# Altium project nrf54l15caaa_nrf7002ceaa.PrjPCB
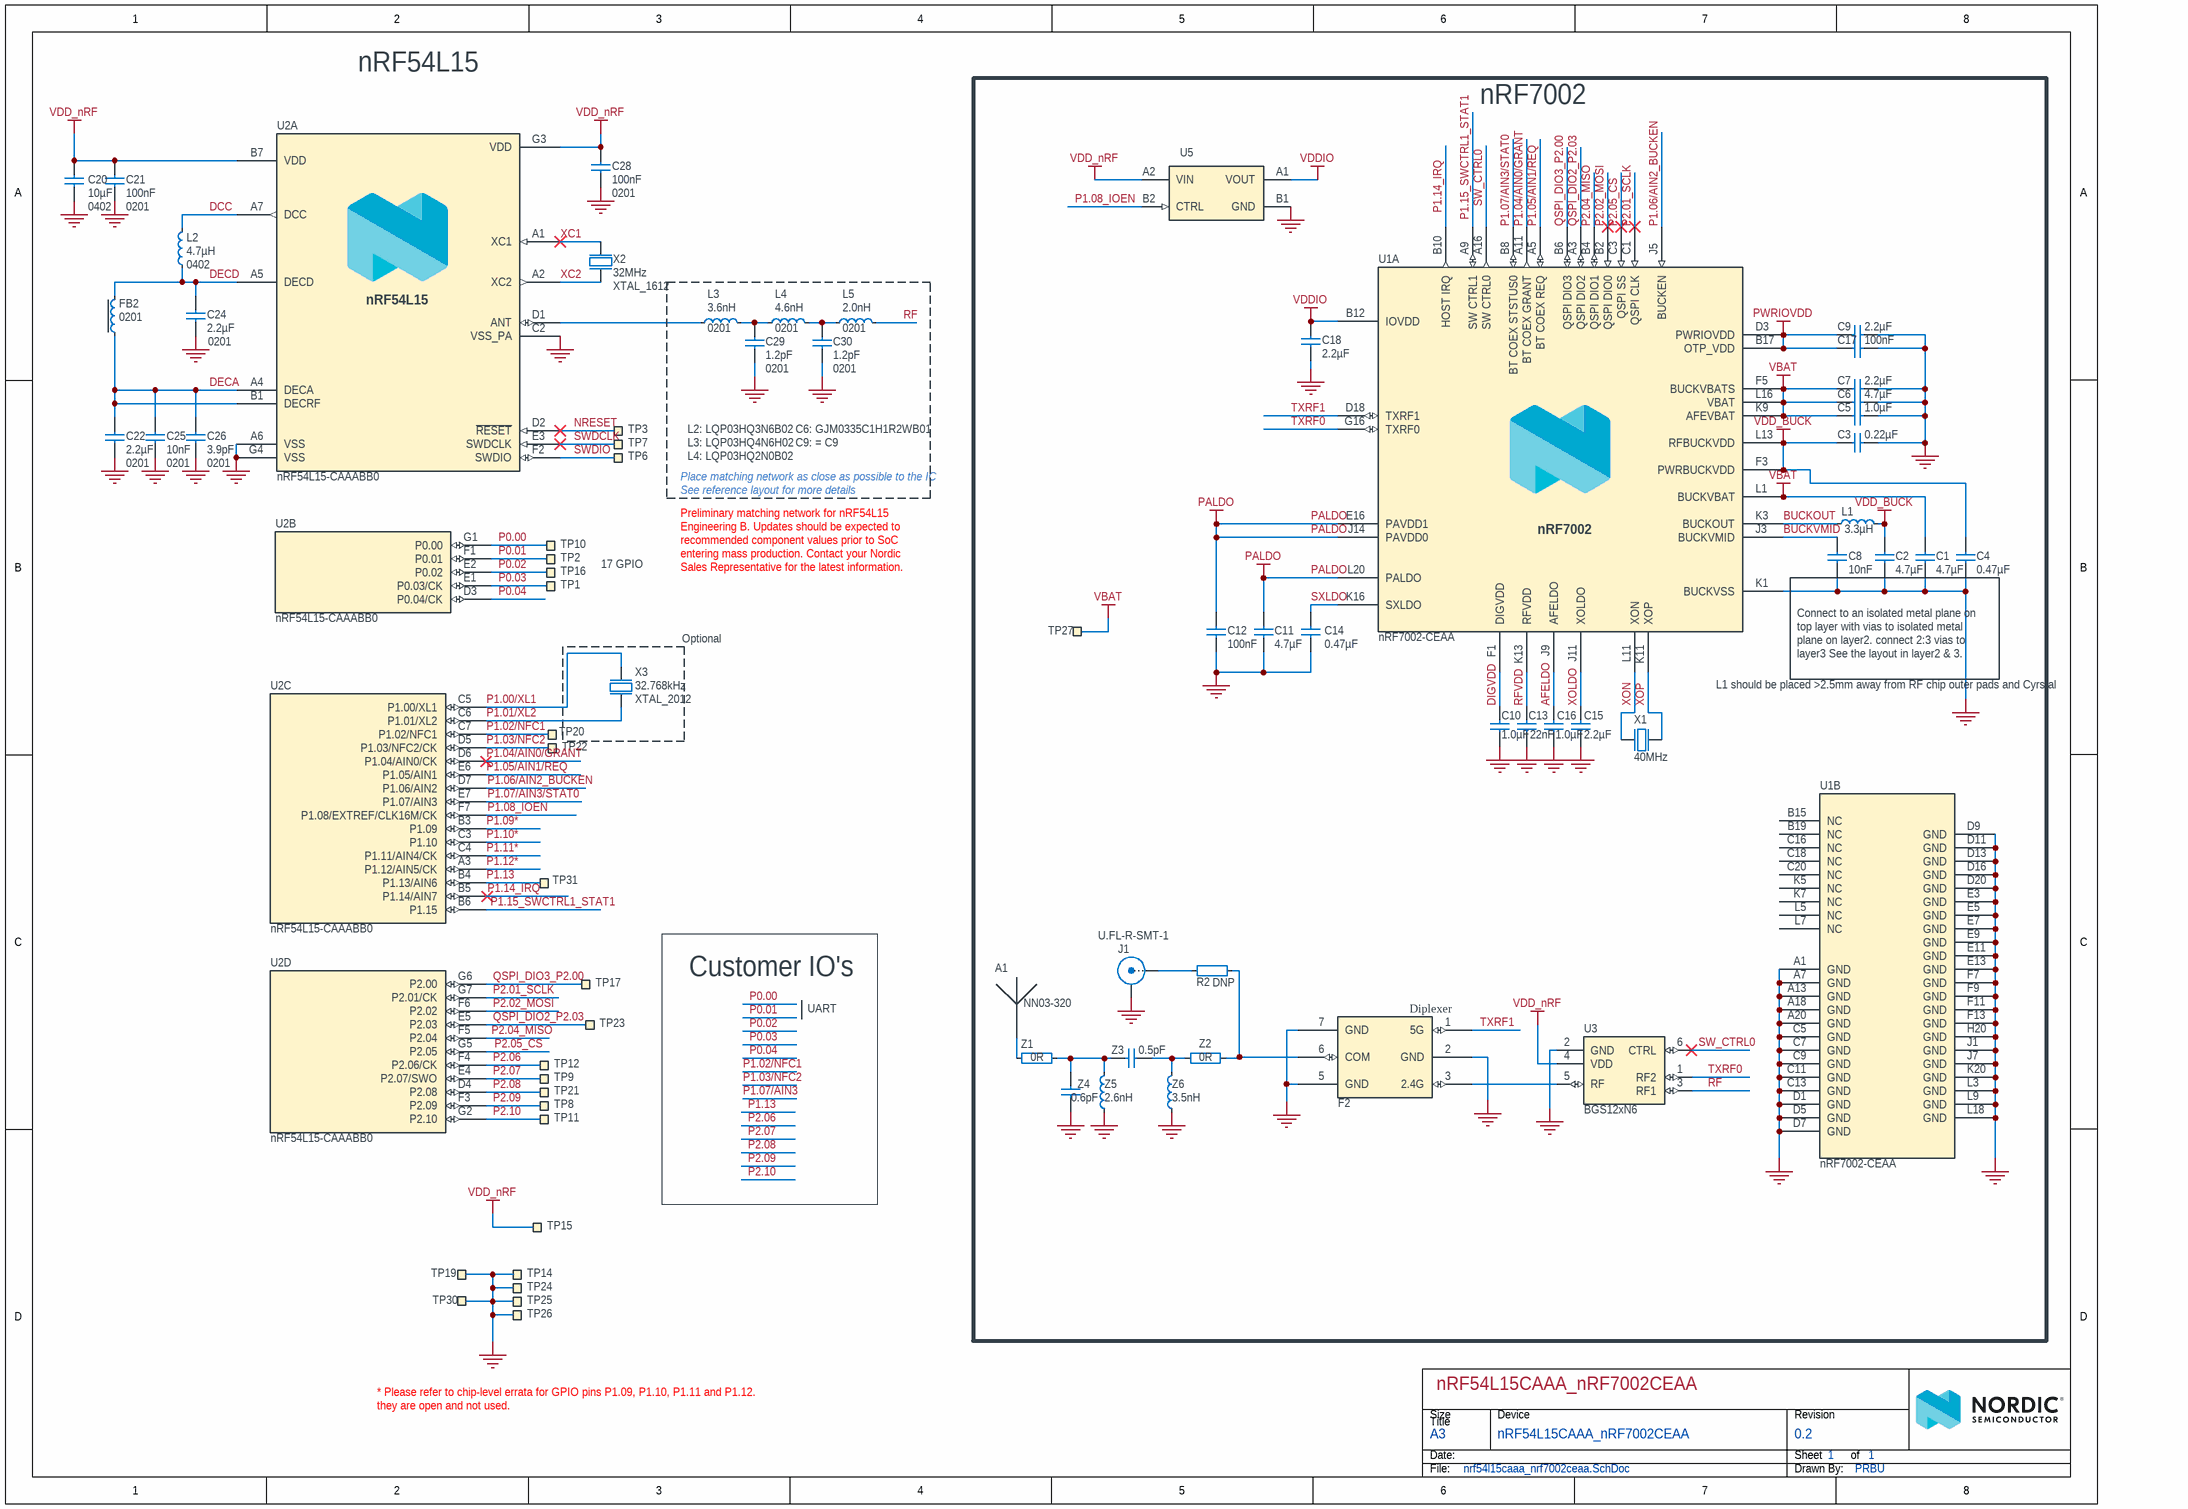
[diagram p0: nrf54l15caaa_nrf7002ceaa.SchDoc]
Revision: 0.2; RefLayoutTitle: nRF54L15CAAA_nRF7002CEAA; Device: nRF54L15CAAA_nRF7002CEAA; Classification: PRELIMINARY
1 sheet, 75 parts. Net scope: global (net labels, ports and power ports of the same name join across sheets).
Board file: nrf54l15caaa_nrf7002ceaa.PcbDoc

## Sheet nrf54l15caaa_nrf7002ceaa.SchDoc
size A3; Organization: Nordic Semiconductor; Revision: 0.2; SheetNumber: 1; SheetTotal: 1; DrawnBy: PRBU; DocumentSize: A3

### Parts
A1  NN03-320  [NN03-320]
C1  4.7µF  [CAPC1608X06L]
C2  4.7µF  [CAPC1608X06L]
C3  0.22µF  [CAPC0603X03L_C]
C4  0.47µF  [CAPC0603X03L_C]
C5  1.0µF  [CAPC1005X04L]
C6  4.7µF  [CAPC1608X06L]
C7  2.2µF  [CAPC1608X06L]
C8  10nF  [CAPC0603X03L_C]
C9  2.2µF  [CAPC1005X04L]
C10  1.0µF  [CAPC1005X04L]
C11  4.7µF  [CAPC1608X06L]
C12  100nF  [CAPC0603X03L_C]
C13  22nF  [CAPC0603X03L_C]
C14  0.47µF  [CAPC0603X03L_C]
C15  2.2µF  [CAPC0603X03L_C]
C16  1.0µF  [CAPC1005X04L]
C17  100nF  [CAPC0603X03L_C]
C18  2.2µF  [CAPC1005X04L]
C20  10µF  Footprint Doc: 0402  [CAPC1005X04L]
C21  100nF  Footprint Doc: 0201  [CAPC0603X03L_C]
C22  2.2µF  Footprint Doc: 0201  [CAPC0603X03L_C]
C24  2.2µF  Footprint Doc: 0201  [CAPC0603X03L_C]
C25  10nF  Footprint Doc: 0201  [CAPC0603X03L_C]
C26  3.9pF  Footprint Doc: 0201  [CAPC0603X03L_C]
C28  100nF  Footprint Doc: 0201  [CAPC0603X03L_C]
C29  1.2pF  Footprint Doc: 0201  [CAPC0603X03L_C]
C30  1.2pF  Footprint Doc: 0201  [CAPC0603X03L_C]
F2  LFD_5G_Diplexer  [CAF-50P160X80-6N]  (value not drawn)
FB2  Footprint Doc: 0201  [INDC0603X03L_C]  (hidden comment: 120R/0.2A)
J1  U.FL-R-SMT-1  [COAXIAL RF U.FL-R-SMT-1]
L1  3.3µH  [INDC2520X10N]
L2  4.7µH  Footprint Doc: 0402  [INDC1005X04L]
L3  3.6nH  Footprint Doc: 0201  [INDC0603X03L_C]
L4  4.6nH  Footprint Doc: 0201  [INDC0603X03L_C]
L5  2.0nH  Footprint Doc: 0201  [INDC0603X03L_C]
R2  Assembly: DNP  [RESC1005X04L]  (hidden comment: 0R)
TP1  CH  [Castellated_Hole_0.5mm]  (value not drawn)  (no BOM)
TP2  CH  [Castellated_Hole_0.5mm]  (value not drawn)  (no BOM)
TP3  CH  [Castellated_Hole_0.5mm]  (value not drawn)  (no BOM)
TP6  CH  [Castellated_Hole_0.5mm]  (value not drawn)  (no BOM)
TP7  CH  [Castellated_Hole_0.5mm]  (value not drawn)  (no BOM)
TP8  CH  [Castellated_Hole_0.5mm]  (value not drawn)  (no BOM)
TP9  CH  [Castellated_Hole_0.5mm]  (value not drawn)  (no BOM)
TP10  CH  [Castellated_Hole_0.5mm]  (value not drawn)  (no BOM)
TP11  CH  [Castellated_Hole_0.5mm]  (value not drawn)  (no BOM)
TP12  CH  [Castellated_Hole_0.5mm]  (value not drawn)  (no BOM)
TP14  CH  [Castellated_Hole_0.5mm]  (value not drawn)  (no BOM)
TP15  CH  [Castellated_Hole_0.5mm]  (value not drawn)  (no BOM)
TP16  CH  [Castellated_Hole_0.5mm]  (value not drawn)  (no BOM)
TP17  CH  [Castellated_Hole_0.5mm]  (value not drawn)  (no BOM)
TP19  CH  [Castellated_Hole_0.5mm]  (value not drawn)  (no BOM)
TP20  CH  [Castellated_Hole_0.5mm]  (value not drawn)  (no BOM)
TP21  CH  [Castellated_Hole_0.5mm]  (value not drawn)  (no BOM)
TP22  CH  [Castellated_Hole_0.5mm]  (value not drawn)  (no BOM)
TP23  CH  [Castellated_Hole_0.5mm]  (value not drawn)  (no BOM)
TP24  CH  [Castellated_Hole_0.5mm]  (value not drawn)  (no BOM)
TP25  CH  [Castellated_Hole_0.5mm]  (value not drawn)  (no BOM)
TP26  CH  [Castellated_Hole_0.5mm]  (value not drawn)  (no BOM)
TP27  CH  [Castellated_Hole_0.5mm]  (value not drawn)  (no BOM)
TP30  CH  [Castellated_Hole_0.5mm]  (value not drawn)  (no BOM)
TP31  CH  [Castellated_Hole_0.5mm]  (value not drawn)  (no BOM)
U1  nRF7002-CEAA  [nRF7002_WLCSP_R2]  (parts A,B of 2)
U2  nRF54L15-CAAABB0  [BGA49C30P7x7_2245X2451X48]  (parts A,B,C,D of 4)
U3  BGS12xN6  [TSNP-6-8]
U5  TCK106AG  [BGA4C40P2X2_76X76X62]  (value not drawn)
X1  40MHz  [BT-XTAL_1612]
X2  32MHz  Footprint Doc: XTAL_1612  [BT-XTAL_1612]
X3  32.768kHz  [XTAL_2012]
Z1  0R  [RESC1005X04L]
Z2  0R  [RESC1005X04L]
Z3  0.5pF  [CAPC1005X04L]
Z4  0.6pF  [CAPC1005X04L]
Z5  2.6nH  [INDC1005X04L_WW]
Z6  3.5nH  [INDC1005X04L_WW]

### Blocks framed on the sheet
nRF7002: A1 C1-C18 F2 J1 L1 R2 TP27 U1 U3 U5 X1 Z1-Z6
Optional: X3

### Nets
GND: C1.1 C2.1 C3.1 C4.1 C5.2 C6.1 C7.1 C8.1 C9.2 C10.2 C11.1 C12.1 C13.1 C14.1 C15.1 C16.1 C17.1 C18.1 C20.1 C21.2 C22.1 C24.1 C25.1 C26.1 C28.2 C29.1 C30.1 F2.2(GND) F2.5(GND) F2.7(GND) J1.2(Y) TP14.1 TP19.1 TP24.1 TP25.1 TP26.1 TP30.1 U1.A1(GND) U1.A7(GND) U1.A13(GND) U1.A18(GND) U1.A20(GND) U1.C5(GND) U1.C7(GND) U1.C9(GND) U1.C11(GND) U1.C13(GND) U1.D1(GND) U1.D5(GND) U1.D7(GND) U1.D9(GND) U1.D11(GND) U1.D13(GND) U1.D16(GND) U1.D20(GND) U1.E3(GND) U1.E5(GND) U1.E7(GND) U1.E9(GND) U1.E11(GND) U1.E13(GND) U1.F7(GND) U1.F9(GND) U1.F11(GND) U1.F13(GND) U1.H20(GND) U1.J1(GND) U1.J7(GND) U1.K1(BUCKVSS) U1.K20(GND) U1.L3(GND) U1.L9(GND) U1.L18(GND) U2.A6(VSS) U2.C2(VSS_PA) U2.G4(VSS) U3.2(GND) U5.B1(GND) X1.2(GND) X1.4(GND) X2.2(GND) X2.4(GND) Z4.2 Z5.1 Z6.1
PALDO: C11.2 C12.2 U1.E16(PAVDD1) U1.J14(PAVDD0) U1.L20(PALDO)
PWRIOVDD: C9.1 C17.2 U1.B17(OTP_VDD) U1.D3(PWRIOVDD)
VBAT: C1.2 C5.1 C6.2 C7.2 TP27.1 U1.F5(BUCKVBATS) U1.K9(AFEVBAT) U1.L1(BUCKVBAT) U1.L16(VBAT)
VDD_BUCK: C2.2 C3.2 C4.2 L1.2 U1.F3(PWRBUCKVDD) U1.L13(RFBUCKVDD)
VDD_nRF: C20.2 C21.1 C28.1 TP15.1 U2.B7(VDD) U2.G3(VDD) U3.4(VDD) U5.A2(VIN)
VDDIO: C18.2 U1.B12(IOVDD) U5.A1(VOUT)
AFELDO: C16.2 U1.J9(AFELDO)
BUCKOUT: L1.1 U1.K3(BUCKOUT)
BUCKVMID: C8.2 U1.J3(BUCKVMID)
DCC: L2.1 U2.A7(DCC)
DECA: C22.2 C25.2 C26.2 FB2.2 U2.A4(DECA) U2.B1(DECRF)
DECD: C24.2 FB2.1 L2.2 U2.A5(DECD)
DIGVDD: C10.1 U1.F1(DIGVDD)
NRESET: TP3.1 U2.D2(~{RESET})
P0.00: TP10.1 U2.G1(P0.00)
P0.01: TP2.1 U2.F1(P0.01)
P0.02: TP16.1 U2.E2(P0.02)
P0.03: TP1.1 U2.E1(P0.03/CK)
P0.04: U2.D3(P0.04/CK)
P1.00/XL1: U2.C5(P1.00/XL1) X3.2(out)
P1.01/XL2: U2.C6(P1.01/XL2) X3.1(inp)
P1.02/NFC1: TP20.1 U2.C7(P1.02/NFC1)
P1.03/NFC2: TP22.1 U2.D5(P1.03/NFC2/CK)
P1.04/AIN0/GRANT: U1.A11(BT_COEX_GRANT) U2.D6(P1.04/AIN0/CK)
P1.05/AIN1/REQ: U1.A5(BT_COEX_REQ) U2.E6(P1.05/AIN1)
P1.06/AIN2_BUCKEN: U1.J5(BUCKEN) U2.D7(P1.06/AIN2)
P1.07/AIN3/STAT0: U1.B8(BT_COEX_STSTUS0) U2.E7(P1.07/AIN3)
P1.08_IOEN: U2.F7(P1.08/EXTREF/CLK16M/CK) U5.B2(CTRL)
P1.09*: U2.B3(P1.09)
P1.10*: U2.C3(P1.10)
P1.11*: U2.C4(P1.11/AIN4/CK)
P1.12*: U2.A3(P1.12/AIN5/CK)
P1.13: TP31.1 U2.B4(P1.13/AIN6)
P1.14_IRQ: U1.B10(HOST_IRQ) U2.B5(P1.14/AIN7)
P1.15_SWCTRL1_STAT1: U1.A9(SW_CTRL1) U2.B6(P1.15)
P2.01_SCLK: U1.C1(QSPI_CLK) U2.G7(P2.01/CK)
P2.02_MOSI: U1.B2(QSPI_DIO0) U2.F6(P2.02)
P2.04_MISO: U1.B4(QSPI_DIO1) U2.F5(P2.04)
P2.05_CS: U1.C3(QSPI_SS) U2.G5(P2.05)
P2.06: TP12.1 U2.F4(P2.06/CK)
P2.07: TP9.1 U2.E4(P2.07/SWO)
P2.08: TP21.1 U2.D4(P2.08)
P2.09: TP8.1 U2.F3(P2.09)
P2.10: TP11.1 U2.G2(P2.10)
QSPI_DIO2_P2.03: TP23.1 U1.A3(QSPI_DIO2) U2.E5(P2.03)
QSPI_DIO3_P2.00: TP17.1 U1.B6(QSPI_DIO3) U2.G6(P2.00)
RF: L5.2 U3.3(RF1)
RFVDD: C13.2 U1.K13(RFVDD)
SW_CTRL0: U1.A16(SW_CTRL0) U3.6(CTRL)
SWDCLK: TP7.1 U2.E3(SWDCLK)
SWDIO: TP6.1 U2.F2(SWDIO)
SXLDO: C14.2 U1.K16(SXLDO)
TXRF0: U1.G16(TXRF0) U3.1(RF2)
TXRF1: F2.1(5G) U1.D18(TXRF1)
XC1: U2.A1(XC1) X2.1(inp)
XC2: U2.A2(XC2) X2.3(out)
XOLDO: C15.2 U1.J11(XOLDO)
XON: U1.L11(XON) X1.1(inp)
XOP: U1.K11(XOP) X1.3(out)
NetA1_4: A1.4(Feed1) Z1.2
NetC29_2: C29.2 L3.2 L4.1
NetC30_2: C30.2 L4.2 L5.1
NetF2_3: F2.3(2.4G) U3.5(RF)
NetF2_6: F2.6(COM) R2.2 Z2.2
NetJ1_1: J1.1(X) R2.1
NetL3_1: L3.1 U2.D1(ANT)
NetZ1_1: Z1.1 Z3.1 Z4.1 Z5.2
NetZ2_1: Z2.1 Z3.2 Z6.2

Not connected (* = marked no-connect by the designer): A1 1(NC) 2(GND) 3(Feed2); U1 B15(NC) B19(NC) C16(NC) C18(NC) C20(NC) K5(NC) K7(NC) L5(NC) L7(NC); U3 8(NC)

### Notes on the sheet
- nRF54L15
- L2: LQP03HQ3N6B02
- L3: LQP03HQ4N6H02
- C6: GJM0335C1H1R2WB01
- C9: = C9
- Place matching network as close as possible to the IC
- See reference layout for more details
- L4: LQP03HQ2N0B02
- 17 GPIO
- Preliminary matching network for nRF54L15 Engineering B. Updates should be expected to recommended component values prior to SoC entering mass production. Contact your Nordic Sales Representative for the latest information.
- (near U1) L1 should be placed >2.5mm away from RF chip outer pads and Cyrstal
- Connect to an isolated metal plane on top layer with vias to isolated metal plane on layer2. connect 2:3 vias to layer3 See the layout in layer2 & 3.
- Customer IO's
- UART
- (near F2) Diplexer
- * Please refer to chip-level errata for GPIO pins P1.09, P1.10, P1.11 and P1.12. they are open and not used.
- Size
- Date:
- A3
- Title
- Device
- Sheet         of
- Revision
- File:
- Drawn By:

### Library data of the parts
A1 = NN03-320: Dual-Band GNSS and Wi-Fi/BluetoothAntenna; Manufacturer: Ignion; Component Status: Active; Pad Count: 4
C1 C2 C6 C11 = C0603-4µ7-25V-X6S-GRM188C81E475KE11: Capacitor, Ceramic, 4.7µF 25V X6S 0603,±10%; Manufacturer: Murata; Manufacturer Part Number: GRM188C81E475KE11D; Pad Count: 2; Component Status: Active
C3 = C0201-220n-10V-X5R-GRM033R61A224KE90: Capacitor, Ceramic, 0.22µF 10V X5R 0201, ±10%; Manufacturer: Murata; Manufacturer Part Number: GRM033R61A224KE90D; Pad Count: 2; Component Status: Active
C4 C14 = C0201-470n-6.3V-X5R-GRM033R60J474KE90: Capacitor, Ceramic, 0.47µF 6.3V X5R 0201,±10%; Manufacturer: Murata; Manufacturer Part Number: GRM033R60J474KE90D; Pad Count: 2; Component Status: Active
C5 = C0402-1µ0-35V-X5R-GRM155R6YA105KE11: Capacitor, Ceramic, 1.0µF 35V X5R 0402,±10%; Manufacturer: Murata; Manufacturer Part Number: GRM155R6YA105KE11D; Pad Count: 2; Component Status: Active
C7 = C0603-2µ2-16V-X7S-GRM188C71C225KE11: Capacitor, Ceramic, 2.2µF 16V X7S 0603,±10%; Manufacturer: Murata; Manufacturer Part Number: GRM188C71C225KE11D; Pad Count: 2; Component Status: Active
C8 = C0201-10n-16V-X7R-GRM033R71C103KE14: Capacitor, Ceramic, 10nF 16V X7R 0201,±10%; Manufacturer: Murata; Manufacturer Part Number: GRM033R71C103KE14D; Pad Count: 2; Component Status: Active
C9 = C0402-2µ2-25V-X5R-GRM155R61E225KE11: Capacitor, Ceramic, 2.2µF 25V X5R 0402,±10%; Manufacturer: Murata; Manufacturer Part Number: GRM155R61E225KE11D; Pad Count: 2; Component Status: Active
C10 = C0402-1µ0-16V-X6S-GRM155C81C105KE11J: Capacitor, Ceramic, 1.0µF 16V X6S 0402,±10%; Manufacturer: Murata; Pad Count: 2; Component Status: Active
C12 C17 = C0201-100n-16V-X7S-GRM033C71C104KE14: Capacitor, Ceramic, 100nF 16V X7S 0201,±10%; Manufacturer: Murata; Manufacturer Part Number: GRM033C71C104KE14D; Pad Count: 2; Component Status: Active
C13 = C0201-22n-10V-X5R-GRM033R61A223KE84: Capacitor, Ceramic, 22nF 10V X5R 0201,±10%; Manufacturer: Murata; Manufacturer Part Number: GRM033R61A223KE84D; Pad Count: 2; Component Status: Active
C15 = C0201-2µ2-10V-X5R-GRM033R61A225KE47: Capacitor, Ceramic, 2.2µF 10V X5R 0201,±10%; Manufacturer: Murata; Manufacturer Part Number: GRM033R61A225KE47D; Pad Count: 2; Component Status: Active
C16 = C0402-1µ0-10V-X7S-GRM155C71A105KE11: Capacitor, Ceramic, 1.0µF 10V X7S 0402,±10%; Manufacturer: Murata; Manufacturer Part Number: GRM155C71A105KE11D; Pad Count: 2; Component Status: Active
C18 = C0402-2µ2-16V-X6S-M: CAP MLCC 2.2UF 16V X6S 0402; Manufacturer: Taiyo Yuden; Manufacturer Part Number: EMK105CC6225KV-F; Component Status: Active; Pad Count: 2
C20 = C0402-10µF-6.3V-X6S: Capacitor, X6S, ±20%, 6.3V; Manufacturer: N.A.; Component Status: Active; Pad Count: 2
C21 C28 = C0201-100n-10V-X7R: Capacitor, X7R, ±10%; Manufacturer: N.A.; Pad Count: 2; Component Status: Active
C22 C24 = C0201-2µ2-2.5V-X6T-GRM033D80E225ME47D: Capacitor, Ceramic, 2.2µF 2.5V X6T 0201,±20%; Manufacturer: Murata; Component Status: Active; Pad Count: 2
C25 = C0201-10n-6.3V-X7R: Capacitor, X7R, 6.3V; Manufacturer: Murata; Manufacturer Part Number: GRM033R70J103KA01D; Component Status: Active; Pad Count: 2
C26 = C0201-3.9p-HQ-Murata: Capacitor, NP0, ±0.05pF, 25V; Manufacturer: Murata; Manufacturer Part Number: GJM0333C1E3R9WB01; Component Status: Active; Pad Count: 2
C29 C30 = C0201-1.2p-HQ-Murata: Capacitor, NP0, ±0.05pF, 50V; Manufacturer: Murata; Manufacturer Part Number: GJM0335C1H1R2WB01D; Component Status: Active; Pad Count: 2
F2 = LFD182G45DCHD277: Signal Conditioning 2.4GHz and 5GHz Diplexer; Manufacturer: Murata; Component Status: Active; Pad Count: 6
FB2 = FB0201-120R@100M-200mA-BLM03AG121SN1D: Ferrite Bead, 120 Ohm @ 100MHz, 200mA, 500 mOhm Max; Manufacturer: Murata; Component Status: Active; Pad Count: 2
J1 = U.FL-R-SMT-1: Ultra Small Surface Mount Coaxial Connectors, 50 Ohm, SMD; Manufacturer: Hirose; Component Status: Active; Pad Count: 3
L1 = L1008-3µ3-LQM2HPN3R3MGCL: Inductor, 1A, ±20%, 200mOhm; Manufacturer: Murata; Pad Count: 2; Component Status: Active
L2 = L0402-4µ7-PLEA67BCA4R7M-1PT00: Inductor, 300mA, ±20%, 1.08R; Manufacturer: TDK Corporation; Component Status: Active; Pad Count: 2
L3 = L0201-3n6-HQ-Murata: Inductor, 500mA, ±0.1ｎH, 170mOhm; Manufacturer: Murata; Manufacturer Part Number: LQP03HQ3N6B02; Component Status: Active; Pad Count: 2
L4 = L0201-4n6-HQ-Murata: Inductor, 400mA, ±3%, 250mOhm; Manufacturer: Murata; Manufacturer Part Number: LQP03HQ4N6H02; Component Status: Active; Pad Count: 2
L5 = L0201-2n0-HQ-Murata: Inductor, 600mA, ±0.1ｎH, 120mOhm; Manufacturer: Murata; Manufacturer Part Number: LQP03HQ2N0B02; Component Status: Active; Pad Count: 2
R2 = R0402-0R: Resistor, ±5%, 0.063W; Manufacturer: N.A.; Component Status: Active; Pad Count: 2
TP1-TP3 TP6-TP12 TP14-TP17 TP19-TP27 TP30 TP31 = Castellated Hole 0.5mm: Manufacturer: N.A.; Component Status: Active; Pad Count: 1
U1 = nRF7002-CEAA: Wi-fi Dual Band Companion chip WLCSP; Manufacturer: Nordic Semiconductor; Component Status: Active; Pad Count: 49
U2 = nRF54L15-CAAABB0: Multi-protocol Bluetooth Low Energy, IEEE 802.15.4, ANT and 2.4GHz proprietary system-on-chip; Manufacturer: Nordic Semiconductor; Component Status: Active; Pad Count: 47
U3 = BGS12SN6: Wideband SPDT RF Switch, 50MHz-6GHz. Max 30dBm, 1.8-3.5V; Manufacturer: Infineon Technologies; Manufacturer Part Number: BGS12SN6E6327XTSA1; Component Status: Active; Pad Count: 6
U5 = TCK106AG: 1.0 A Load Switch IC with Slew Rate Control Driver in Ultra Small Package; Manufacturer: Toshiba; Manufacturer Part Number: TCK106AG,LF; Pad Count: 4
X1 = XTAL_SMD1612_40MHz_8p_40_85: XTAL SMD 1612, 40MHz, Cl=8pF, Total Tol: ±10ppm, -40-85C; Manufacturer: Abracon Corporation; Manufacturer Part Number: ABM12W-40.0000MHZ-8-D1X-T3; Pad Count: 4; Component Status: Active
X2 = XTAL_SMD1612_32MHz_8pF_Kyocera: XTAL SMD 1612, 32MHz, Cl=8pF, Tot: ±40ppm, Aging: ±1ppm/year; Manufacturer Part Number: CX1612DB32000D0WZRC3; Component Status: Active; Pad Count: 4
X3 = XTAL_SMD2012_32.768kHz_9pF_TXC: XTAL SMD 2012, 32.768kHz, 9pF, ±20ppm; Manufacturer: TXC Corporation; Manufacturer Part Number: 9HT11-32.768KDZC-T; Component Status: Active; Pad Count: 2
Z1 Z2 = R0402-0R: Resistor, ±5%, 0.063W; Manufacturer: N.A.; Pad Count: 2; Component Status: Active
Z3 = C0402-0.5p-HQ-Murata: Capacitor, NP0, ±0.05pF, 50V; Manufacturer: Murata; Manufacturer Part Number: GJM1555C1HR50WB01; Pad Count: 2; Component Status: Active
Z4 = C0402-0.6p: Chip Cap 0402; Manufacturer: N.A.; Pad Count: 2; Component Status: Active
Z5 = L0402-2n6-Wirewound-Murata: Inductor, 850mA, ±0.1nH, 50mΩ; Manufacturer: Murata; Manufacturer Part Number: LQW15AN2N6B00; Component Status: Active; Pad Count: 2
Z6 = L0402-3n5-Wirewound-Murata: Inductor, 900mA, ±0.2nH, 40mΩ; Manufacturer: Murata; Manufacturer Part Number: LQW15AN3N5C10; Component Status: Active; Pad Count: 2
